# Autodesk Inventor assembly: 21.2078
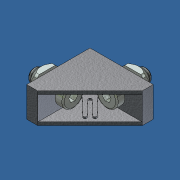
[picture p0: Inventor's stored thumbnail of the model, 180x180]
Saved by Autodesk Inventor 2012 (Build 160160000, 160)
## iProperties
Created: 2012-10
Part Number: 21.2078
Document SubType Name: Assembly
Designer: Administrator
Description: Angle 19 GD-Z
Mass: 59.7344 g
Surface Area: 95.2241 cm^2
Volume: 14.1823 cm^3
Density: 4.2119 g/cm^3
Vendor: S
Author: Administrator
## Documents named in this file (4)
- Y:\INVENTOR LIBRARIES\PARTS LIBRARY\FASTENING ELEMENTS\21.2078 Angle 19 GD-Z.iam
- Y:\INVENTOR LIBRARIES\PARTS LIBRARY\FASTENING ELEMENTS\SUBCOMPONENTS\21.2078_1 Angle 19.ipt
- Y:\INVENTOR LIBRARIES\PARTS LIBRARY\FASTENING ELEMENTS\SCREWS CAP\21.1202 M8X20.ipt
- Y:\INVENTOR LIBRARIES\PARTS LIBRARY\FASTENING ELEMENTS\NUTS\21.1351 M8 SQUARE NUT.ipt
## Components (5 placed, 3 different names)
1. 21.2078_1 Angle 19:1 — Mate:1, Mate:2, Mate:3, Mate:4, Mate:5, Mate:6, Mate:8, Mate:9, Angle:1, Angle:2
2. 21.1202  M8 x 20:1 — Mate:1, Mate:2, Mate:5, Mate:10
3. 21.1202  M8 x 20:2 — Mate:3, Mate:4, Mate:6, Mate:7
4. 21.1351 M8 SQUARE NUT:1 — Mate:7, Mate:8, Angle:2
5. 21.1351 M8 SQUARE NUT:2 — Mate:9, Mate:10, Angle:1
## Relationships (12: Mate 10, Angle 2)
- Mate:1: 21.2078_1 Angle 19:1 ↔ 21.1202  M8 x 20:1
- Mate:2: 21.2078_1 Angle 19:1 ↔ 21.1202  M8 x 20:1
- Mate:3: 21.2078_1 Angle 19:1 ↔ 21.1202  M8 x 20:2
- Mate:4: 21.2078_1 Angle 19:1 ↔ 21.1202  M8 x 20:2
- Mate:5: 21.2078_1 Angle 19:1 ↔ 21.1202  M8 x 20:1
- Mate:6: 21.2078_1 Angle 19:1 ↔ 21.1202  M8 x 20:2
- Mate:7: 21.1202  M8 x 20:2 ↔ 21.1351 M8 SQUARE NUT:1
- Mate:8: 21.2078_1 Angle 19:1 ↔ 21.1351 M8 SQUARE NUT:1
- Mate:9: 21.2078_1 Angle 19:1 ↔ 21.1351 M8 SQUARE NUT:2
- Mate:10: 21.1202  M8 x 20:1 ↔ 21.1351 M8 SQUARE NUT:2
- Angle:1: 21.2078_1 Angle 19:1 ↔ 21.1351 M8 SQUARE NUT:2
- Angle:2: 21.2078_1 Angle 19:1 ↔ 21.1351 M8 SQUARE NUT:1
